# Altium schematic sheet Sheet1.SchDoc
size A; SheetNumber: 1; SheetTotal: 1; SPICEModelCacheGYLIFTHO: <root> / <DocumentId>GYLIFTHO</DocumentId> / <CacheFrame Number="0"> / <Model Name="1n5408" Kind="MDL"> / <Text>*1N5408 MCE 8/5/97 / *Ref: International Rectifier Digest '94 / *1000V 3000mA 3us Si Diode pkg:DIODE0.4 1,2 / .MODEL 1N5408 D (IS=4.26N RS=14M N=1.7 BV=1E+03 IBV=165U / + CJO=125P VJ=0.75 M=0.333 TT=4.32U)</Text> / </Model> / <Model Name="1n4007" Kind="MDL"> / <Text>*1N4007 MCE 8-16-95 / *1000V 1A Si GenPurpose Diode pkg:DIODE0.4 1,2 / .MODEL 1N4007 D(IS=2.55E-9 RS=0.042 N=1.75 TT=5.76E-6 CJO=1.85E-11 / + VJ=0.75 M=0.333 BV=1000 IBV=9.86E-5 )</Text> / </Model> / <Model Name="cap" Kind="MDL"> / <Text>*Default semiconductor capacitor / .MODEL CAP C()</Text> / </Model> / </CacheFrame> / </root>
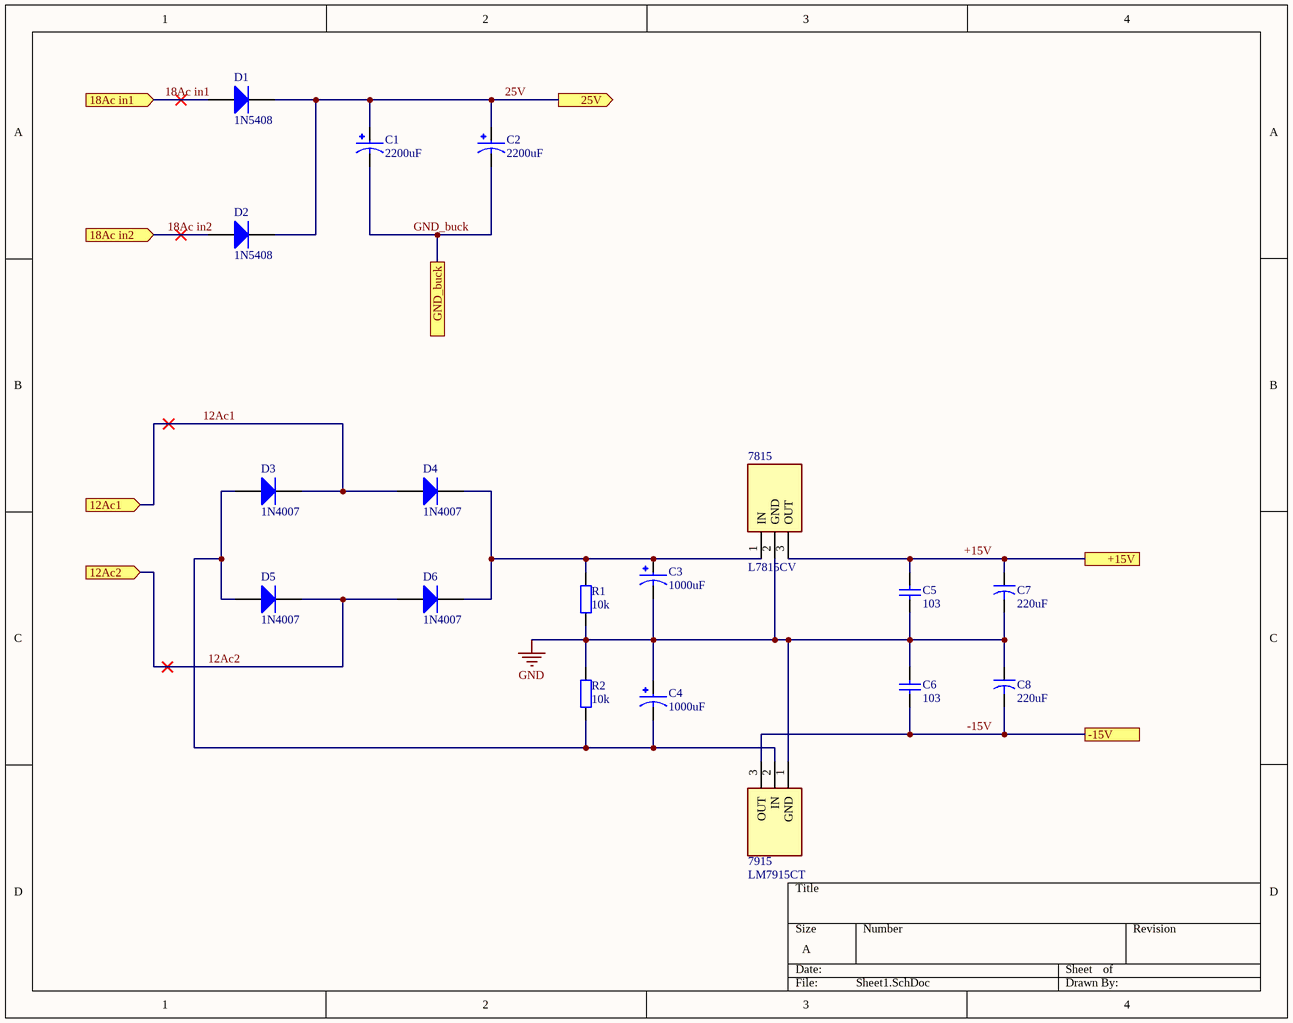
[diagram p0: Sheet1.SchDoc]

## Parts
7815  L7815CV  [TO270P460X1020X2008-3P]
7915  LM7915CT  [TO254P470X1016X2019-3P]
C1  2200uF  [CAPPRD500W60D1250H2500]
C2  2200uF  [CAPPRD500W60D1250H2500]
C3  1000uF  [CAPPRD500W60D1250H2500]
C4  1000uF  [CAPPRD500W60D1250H2500]
C5  103  [CAP_DE2E3SA103MA3BT02F]
C6  103  [CAP_DE2E3SA103MA3BT02F]
C7  220uF  [CAPR5-4X5]
C8  220uF  [CAPR5-4X5]
D1  1N5408  [DO-201AD]
D2  1N5408  [DO-201AD]
D3  1N4007  [DO-41]
D4  1N4007  [DO-41]
D5  1N4007  [DO-41]
D6  1N4007  [DO-41]
R1  10k  [AXIAL-0.4]
R2  10k  [AXIAL-0.4]

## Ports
12Ac1 (in), 12Ac2 (in), 18Ac in1 (in), 18Ac in2 (in), 25V (out), +15V, -15V, GND_buck

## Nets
GND: 7815.2(GND) 7915.1(GND) C3.N C4.P C5.1 C6.2 C7.2 C8.1 R1.1 R2.2
12Ac1: D3.2(K) D4.1(A) ; port 12Ac1
12Ac2: D5.2(K) D6.1(A) ; port 12Ac2
18Ac in1: D1.1(A) ; port 18Ac in1
18Ac in2: D2.1(A) ; port 18Ac in2
25V: C1.P C2.P D1.2(K) D2.2(K) ; port 25V
+15V: 7815.3(OUT) C5.2 C7.1 ; port +15V
-15V: 7915.3(OUT) C6.1 C8.2 ; port -15V
GND_buck: C1.N C2.N ; port GND_buck
Net7815_1: 7815.1(IN) C3.P D4.2(K) D6.2(K) R1.2
Net7915_2: 7915.2(IN) C4.N D3.1(A) D5.1(A) R2.1

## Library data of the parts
7815 = L7815CV: L7815CV, Voltage Regulator, 1.5A 15 V, 3-Pin TO-220; Manufacturer_Name: STMicroelectronics; Geometry.Height: 4.6mm
7915 = LM7915CT: ON Semiconductor LM7915CT Negative Voltage Regulator, 1A, -15 V, +/-4% 3-Pin, TO-220; Manufacturer_Name: onsemi; Geometry.Height: 4.7mm
C1 C2 = EEUFM1C222: 2200ÂµF 16V Aluminum Electrolytic Capacitors Radial, Can 7000 Hrs @ 105Â°C; MF: Panasonic
C3 C4 = EEUHD1H102B: CAP ALUM 1000UF 20% 50V RADIAL; MF: Panasonic; MP: EEU-HD1H102B
C5 C6 = Cap: Capacitor; Value: 100pF
C7 C8 = Cap2: Capacitor; Value: 100pF
D1 D2 = Diode 1N5408: 3 Amp Medium Power Silicon Rectifier Diode
D3-D6 = Diode 1N4007: 1 Amp General Purpose Rectifier
R1 R2 = Res2: Resistor; Value: 1K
